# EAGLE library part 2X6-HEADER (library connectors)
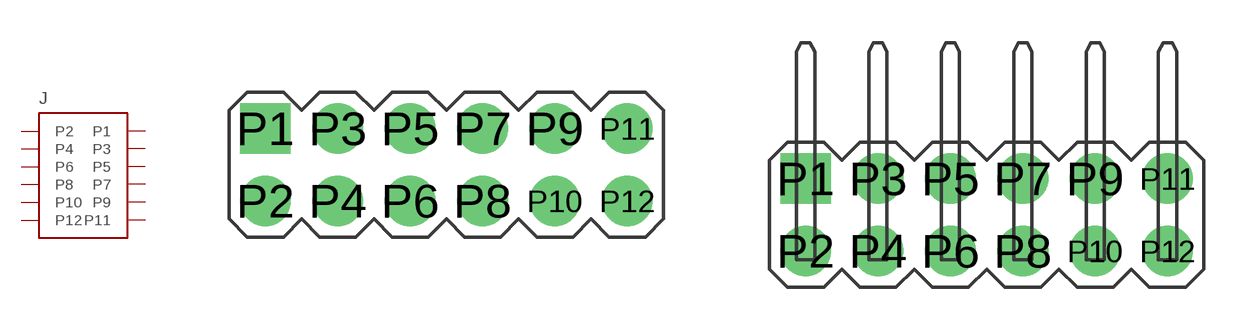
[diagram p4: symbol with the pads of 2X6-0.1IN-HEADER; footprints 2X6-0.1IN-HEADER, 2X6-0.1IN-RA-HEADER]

Designator prefix J

## 2X6-HEADER0.1IN  [2X6-0.1IN-HEADER]
P1  P1  pas
P2  P2  pas
P3  P3  pas
P4  P4  pas
P5  P5  pas
P6  P6  pas
P7  P7  pas
P8  P8  pas
P9  P9  pas
P10  P10  pas
P11  P11  pas
P12  P12  pas

## 2X6-HEADER0.1INRA  [2X6-0.1IN-RA-HEADER]
Pads as for 2X6-0.1IN-HEADER

## 2X6-HEADER2MM  [2X6-2MM-HEADER]
Pads as for 2X6-0.1IN-HEADER

## Footprint 2X6-0.1IN-HEADER (pad centres in mm)
drill 1.05 pad 1.778 square: P1 -6.35,1.27
drill 1.05 pad 1.778 round: P2 -6.35,-1.27; P3 -3.81,1.27; P4 -3.81,-1.27; P5 -1.27,1.27; P6 -1.27,-1.27; P7 1.27,1.27; P8 1.27,-1.27; P9 3.81,1.27; P10 3.81,-1.27; P11 6.35,1.27; P12 6.35,-1.27

## Footprint 2X6-0.1IN-RA-HEADER (pad centres in mm)
drill 1.05 pad 1.778 square: P1 -6.35,1.27
drill 1.05 pad 1.778 round: P2 -6.35,-1.27; P3 -3.81,1.27; P4 -3.81,-1.27; P5 -1.27,1.27; P6 -1.27,-1.27; P7 1.27,1.27; P8 1.27,-1.27; P9 3.81,1.27; P10 3.81,-1.27; P11 6.35,1.27; P12 6.35,-1.27

## Footprint 2X6-2MM-HEADER (pad centres in mm)
drill 0.85 pad 1.4 octagon: P1 -5,1
drill 0.85 pad 1.4 round: P2 -5,-1; P3 -3,1; P4 -3,-1; P5 -1,1; P6 -1,-1; P7 1,1; P8 1,-1; P9 3,1; P10 3,-1; P11 5,1; P12 5,-1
